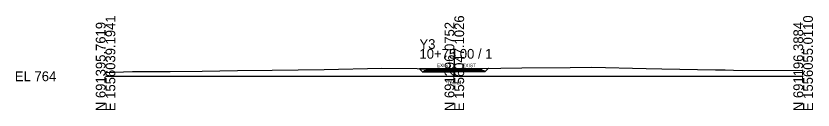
# Model space of a CAD drawing. Extents: x -26 to 203, y -10 to 1517.
# Drawn here: x -25.7 to 202.8, y 490.3 to 517.3 of the extents above; entities that cross this region are included whole.
import ezdxf

# ---------------------------------------------------------------- set-up
doc = ezdxf.new("R2010")
doc.units = 0
for name, color, linetype in [('Exist Cross Section Cell', 7, 'Continuous'), ('Exist XS Center Line Elevation Label', 7, 'Continuous'), ('Exist XS Ground Line', 7, 'Continuous'), ('Prop CMT Pvmt Course 1', 7, 'Continuous'), ('Prop CMT Pvmt Course 2', 7, 'Continuous'), ('Prop CMT Pvmt Course 3', 7, 'Continuous'), ('Prop CMT Pvmt Surface', 7, 'Continuous'), ('Prop CMT Shld Paved Course 1', 7, 'Continuous'), ('Prop CMT Shld Paved Course 2', 7, 'Continuous'), ('Prop CMT Shld Paved Course 3', 7, 'Continuous'), ('Prop CMT Slope Grass', 7, 'Continuous'), ('Prop CMT Subgrade Earthwork', 7, 'Continuous'), ('Prop XS Earthwork Shape', 7, 'Continuous'), ('Prop XS SE Text', 7, 'Continuous')]:
    doc.layers.add(name, color=color, linetype=linetype)

msp = doc.modelspace()

# ---------------------------------------------------------------- linework, layer by layer
at = {"layer": 'Exist Cross Section Cell'}
for p, q in [((100, 500), (100, 507.86)), ((0, 500), (100, 500)), ((100, 500), (200, 500))]:
    msp.add_line(p, q, dxfattribs=at)
at = {"layer": 'Exist XS Ground Line'}
msp.add_lwpolyline([(0, 501.07), (7.69, 501.35), (18.55, 501.34), (27.73, 501.51), (37.87, 501.63), (47.78, 501.8), (62.64, 501.97), (79.23, 502.32), (89.36, 502.2), (92.92, 502.14), (100, 502.21), (107.26, 502.29), (119.36, 502.44), (133.2, 502.5), (139.42, 502.62), (154.99, 502.23), (159.48, 502.12), (174.85, 501.86), (177.64, 501.82), (180.02, 501.76), (200, 501.66)], dxfattribs=at)
at = {"layer": 'Prop CMT Pvmt Course 1'}
msp.add_lwpolyline([(100, 501.96), (100, 502.21)], dxfattribs=at)
msp.add_lwpolyline([(100, 501.96), (100, 502.21)], dxfattribs=at)
at = {"layer": 'Prop CMT Pvmt Course 2'}
msp.add_lwpolyline([(100, 501.63), (100, 501.96)], dxfattribs=at)
msp.add_lwpolyline([(100, 501.63), (100, 501.96)], dxfattribs=at)
at = {"layer": 'Prop CMT Pvmt Course 3'}
msp.add_lwpolyline([(100, 501.29), (100, 501.63)], dxfattribs=at)
msp.add_lwpolyline([(100, 501.29), (100, 501.63)], dxfattribs=at)
at = {"layer": 'Prop CMT Pvmt Surface'}
for points in [[(100, 502.21), (92.41, 502.15)], [(100, 502.21), (107.41, 502.29)]]:
    msp.add_lwpolyline(points, dxfattribs=at)
at = {"layer": 'Prop CMT Shld Paved Course 1'}
for points in [[(100, 502.21), (92.41, 502.15), (92.16, 501.9)], [(92.16, 501.9), (100, 501.96)], [(100, 502.21), (107.41, 502.29), (107.66, 502.04)], [(107.66, 502.04), (100, 501.96)]]:
    msp.add_lwpolyline(points, dxfattribs=at)
at = {"layer": 'Prop CMT Shld Paved Course 2'}
for points in [[(100, 501.96), (92.16, 501.9), (91.82, 501.56)], [(91.82, 501.56), (100, 501.63)], [(100, 501.96), (107.66, 502.04), (108, 501.7)], [(108, 501.7), (100, 501.63)]]:
    msp.add_lwpolyline(points, dxfattribs=at)
at = {"layer": 'Prop CMT Shld Paved Course 3'}
for points in [[(100, 501.63), (91.82, 501.56), (91.32, 501.55), (90.99, 501.21)], [(90.99, 501.21), (100, 501.29)], [(100, 501.63), (108, 501.7), (108.49, 501.7), (108.82, 501.37)], [(108.82, 501.37), (100, 501.29)]]:
    msp.add_lwpolyline(points, dxfattribs=at)
at = {"layer": 'Prop CMT Slope Grass'}
for p, q in [((92.41, 502.15), (90.02, 502.19)), ((107.41, 502.29), (109.77, 502.32))]:
    msp.add_line(p, q, dxfattribs=at)
at = {"layer": 'Prop CMT Subgrade Earthwork'}
for p, q in [((90.02, 502.19), (90.99, 501.21)), ((109.77, 502.32), (108.82, 501.37))]:
    msp.add_line(p, q, dxfattribs=at)
for points in [[(100, 501.29), (90.99, 501.21)], [(100, 501.29), (108.82, 501.37)]]:
    msp.add_lwpolyline(points, dxfattribs=at)
at = {"layer": 'Prop XS Earthwork Shape'}
msp.add_lwpolyline([(107.26, 502.29), (107.41, 502.29), (109.77, 502.32), (108.82, 501.37), (100, 501.29), (90.99, 501.21), (90.02, 502.19), (92.41, 502.15), (92.92, 502.14), (100, 502.21)], close=True, dxfattribs=at)

# ---------------------------------------------------------------- texts
at = {"layer": 'Exist Cross Section Cell'}
for s, p in [('E 1556039.1941', (2.8, 490)), ('E 1556047.1026', (102.8, 490)), ('E 1556055.0110', (202.8, 490)), ('N 691395.7619', (0, 490)), ('N 691296.0752', (100, 490)), ('N 691196.3884', (200, 490))]:
    msp.add_text(s, height=2.8, rotation=90, dxfattribs=at).set_placement(p)
for s, p in [('Y3', (90, 507.86)), ('10+75.00 / 1', (90, 505.06)), ('EL 764', (-26, 498.6))]:
    msp.add_text(s, height=2.8, dxfattribs=at).set_placement(p)
at = {"layer": 'Exist XS Center Line Elevation Label'}
msp.add_text('766.21', height=1, dxfattribs=at).set_placement((97.94, 497.71))
at = {"layer": 'Prop XS SE Text'}
for rotation, p in [(0.458, (94.98, 502.62)), (0.6091, (102.21, 502.59))]:
    msp.add_text('EXIST', height=1, rotation=rotation, dxfattribs=at).set_placement(p)

doc.saveas('drawing.dxf')
